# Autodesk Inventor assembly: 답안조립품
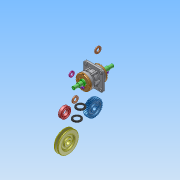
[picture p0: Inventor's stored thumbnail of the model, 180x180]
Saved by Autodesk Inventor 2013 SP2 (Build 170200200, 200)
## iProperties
Created: 2025-08
Part Number: 답안조립품
Document SubType Name: Assembly
Designer: i
Author: i
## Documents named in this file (14)
- C:\Users\i\Desktop\750803V1009\답안조립품.iam
- C:\Users\i\Desktop\750803V1009\본체.ipt
- C:\Users\i\Desktop\750803V1009\깊은 홈 볼 베어링 6005.ipt
- C:\Users\i\Desktop\750803V1009\축.ipt
- C:\Users\i\Desktop\750803V1009\커버.ipt
- C:\Users\i\Desktop\750803V1009\6각 구멍붙이 볼트 M4x10.ipt
- C:\Users\i\Desktop\750803V1009\평행 키 6x6x14.ipt
- C:\Users\i\Desktop\750803V1009\평행 키 6x6x18.ipt
- C:\Users\i\Desktop\750803V1009\V 벨트 풀리.ipt
- C:\Users\i\Desktop\750803V1009\스퍼기어.ipt
- C:\Users\i\Desktop\750803V1009\평 와셔 M14.ipt
- C:\Users\i\Desktop\750803V1009\오일 실 25 38 5.ipt
- C:\Users\i\Desktop\750803V1009\6각 너트 M14x1.ipt
- C:\Users\i\Desktop\750803V1009\스프링 와셔 M14.ipt
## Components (10 placed, 3 different names)
1. 6각 구멍붙이 볼트 M4x10:1
2. 6각 구멍붙이 볼트 M4x10:2
3. 6각 구멍붙이 볼트 M4x10:3
4. 6각 구멍붙이 볼트 M4x10:4
5. 6각 구멍붙이 볼트 M4x10:5
6. 6각 구멍붙이 볼트 M4x10:7
7. 6각 구멍붙이 볼트 M4x10:8
8. 6각 구멍붙이 볼트 M4x10:9
9. V 벨트 풀리:1
10. 6각 너트 M14x1:1
